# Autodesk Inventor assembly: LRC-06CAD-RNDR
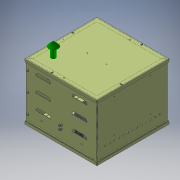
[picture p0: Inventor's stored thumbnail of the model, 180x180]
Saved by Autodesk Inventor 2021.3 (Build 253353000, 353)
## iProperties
load_classification: Lighting
motor: 0 ul
description: 0:0:Open Appearance 6" Adjustable - COB LED
manufacturer: 0:0:The Kirlin Company
model: 0:0:LRC-06CAD
url: 0:0:
Part Number: LRC-06CAD-RNDR
Document SubType Name: Assembly
Designer: JChurch
Author: JChurch
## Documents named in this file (7)
- X:\Revit Files\0000-Un-Zipped\COB\LRC-06CAD-RND\LRC-06CAD-RNDR.iam
- X:\INVENTOR\830\830399-00-00.ipt
- X:\INVENTOR\881\881035-00-00.iam
- X:\INVENTOR\830\830402-00-00.ipt
- X:\INVENTOR\KIRLIN_ENG\725\725075-00-00.ipt
- X:\INVENTOR\750\750300-01-XX.iam
- X:\Revit Files\0000-Un-Zipped\COB\LRC-06CAD-RND\LRC-06CAD-RNDR_Substitute_1.ipt
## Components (6 placed, 6 different names)
1. 830399-00-00:1 — Mate:1, Mate:2, Mate:3, Mate:4, Mate:5, Angle:1, Insert:1
2. 881035-00-00:1 [sub-assembly] — Mate:4, Mate:5, Angle:1, Mate:6, Mate:7, Angle:2
3. 830402-00-00:1 — Mate:6, Mate:7, Angle:2
4. 725075-00-00:1 — Mate:8, Mate:9, Mate:10
5. 750300-01-XX:1 [sub-assembly] — Mate:8, Mate:9, Mate:10, Insert:1
6. LRC-06CAD-RNDR_Substitute_1:1
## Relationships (13: Mate 10, Angle 2, Insert 1)
- Mate:1: 830399-00-00:1
- Mate:2: 830399-00-00:1
- Mate:3: 830399-00-00:1
- Mate:4: 830399-00-00:1 ↔ 881035-00-00:1
- Mate:5: 830399-00-00:1 ↔ 881035-00-00:1
- Angle:1: 830399-00-00:1 ↔ 881035-00-00:1
- Mate:6: 881035-00-00:1 ↔ 830402-00-00:1
- Mate:7: 881035-00-00:1 ↔ 830402-00-00:1
- Angle:2: 881035-00-00:1 ↔ 830402-00-00:1
- Mate:8: 725075-00-00:1 ↔ 750300-01-XX:1
- Mate:9: 725075-00-00:1 ↔ 750300-01-XX:1
- Mate:10: 725075-00-00:1 ↔ 750300-01-XX:1
- Insert:1: 830399-00-00:1 ↔ 750300-01-XX:1
